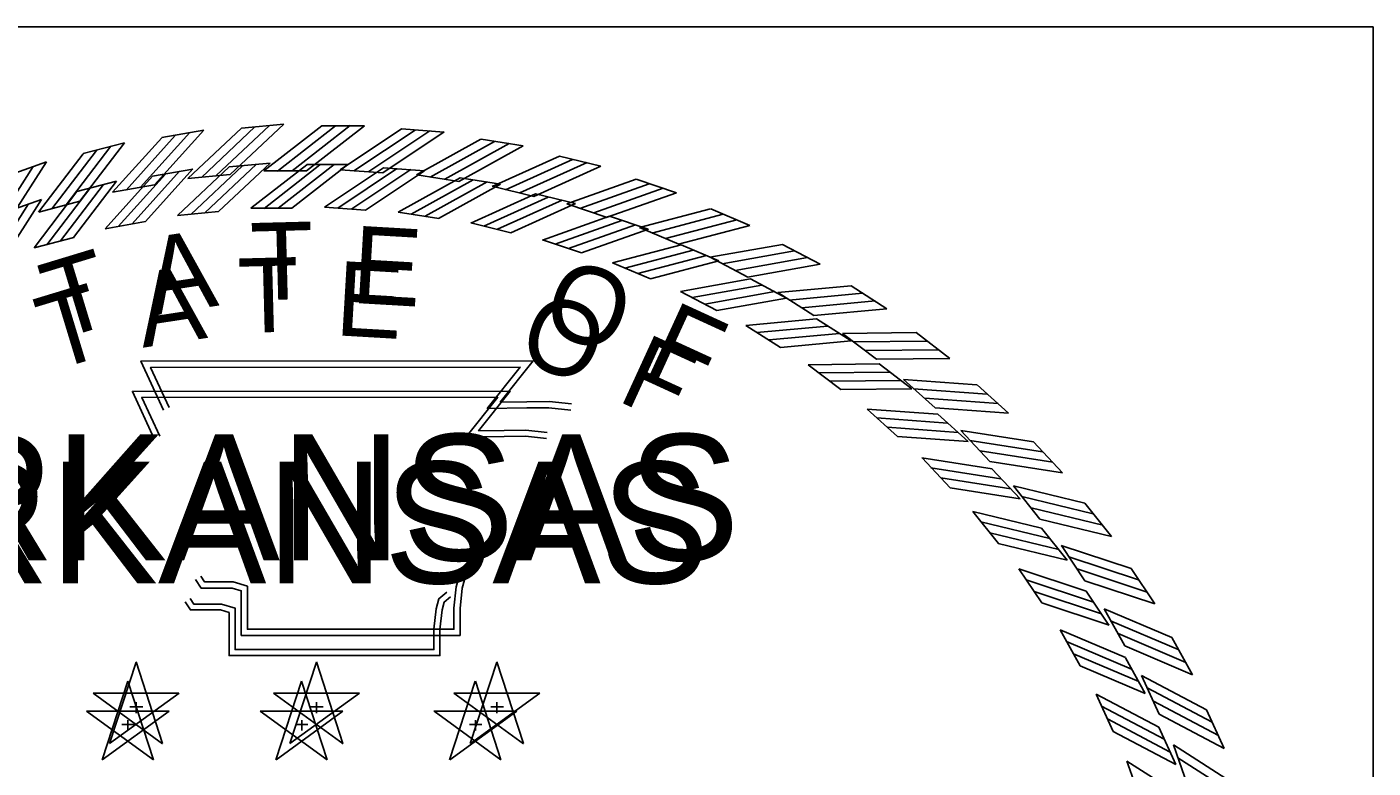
# Model space of a CAD drawing. Extents: x 0 to 1228740, y 0 to 152440.
# Drawn here: x 35.691 to 37.414, y 24.11 to 25.058 of the extents above; entities that cross this region are included whole.
import ezdxf

# ---------------------------------------------------------------- set-up
doc = ezdxf.new("R2010")
doc.units = 0
for name, color, linetype in [('R_No Plot', 7, 'Continuous'), ('STAMP', 7, 'Continuous'), ('STAMP_PP', 7, 'Continuous')]:
    doc.layers.add(name, color=color, linetype=linetype)

msp = doc.modelspace()

# ---------------------------------------------------------------- linework, layer by layer
at = {"layer": 'R_No Plot'}
msp.add_lwpolyline([(34.6722, 25.0583), (37.4139, 25.0583), (37.4139, 22.3166), (34.6722, 22.3166)], close=True, dxfattribs=at)
at = {"layer": 'STAMP'}
for p, q in [((35.8523, 24.8673), (35.9039, 24.8764)), ((35.9503, 24.879), (36.0025, 24.8838)), ((36.0496, 24.882), (36.102, 24.882)), ((36.1477, 24.878), (36.2, 24.8742)), ((35.7555, 24.8475), (35.8062, 24.8609)), ((36.2457, 24.8653), (36.2974, 24.8572)), ((36.3423, 24.8445), (36.3932, 24.8321)), ((35.6607, 24.8198), (35.7101, 24.8373)), ((35.8842, 24.8169), (35.9365, 24.8218)), ((35.9781, 24.8262), (36.0306, 24.8262)), ((36.0723, 24.8277), (36.1247, 24.8238)), ((36.1664, 24.8213), (36.2183, 24.8132)), ((35.7915, 24.8), (35.8432, 24.8091)), ((36.2596, 24.8073), (36.3106, 24.7949)), ((36.4368, 24.8159), (36.4865, 24.7993)), ((35.7005, 24.7754), (35.7513, 24.7888)), ((36.3513, 24.7856), (36.4012, 24.769)), ((36.5286, 24.7795), (36.5768, 24.7589)), ((36.4409, 24.7564), (36.4892, 24.7357)), ((36.6171, 24.7357), (36.6635, 24.7111)), ((36.5279, 24.7198), (36.5743, 24.6953)), ((36.7017, 24.6847), (36.7459, 24.6564)), ((36.6115, 24.6763), (36.6557, 24.6479)), ((36.6912, 24.6259), (36.7329, 24.5941)), ((36.7818, 24.6269), (36.8235, 24.5951)), ((36.7664, 24.5692), (36.8054, 24.534)), ((36.8569, 24.5626), (36.8958, 24.5275)), ((36.8368, 24.5065), (36.8727, 24.4681)), ((36.9264, 24.4924), (36.9622, 24.4542)), ((36.9017, 24.4381), (36.9344, 24.3969)), ((36.9898, 24.4167), (37.0224, 24.3757)), ((36.9608, 24.3646), (36.9899, 24.3209)), ((37.0468, 24.336), (37.0759, 24.2924)), ((37.0136, 24.2865), (37.039, 24.2406)), ((37.097, 24.2509), (37.1223, 24.2051)), ((35.8206, 24.2208), (35.7878, 24.1202)), ((35.8532, 24.1203), (35.8206, 24.2209)), ((36.0429, 24.2208), (36.0101, 24.1202)), ((36.0755, 24.1203), (36.0429, 24.2209)), ((36.2651, 24.2208), (36.2323, 24.1202)), ((36.2978, 24.1203), (36.2652, 24.2209)), ((37.0597, 24.2043), (37.0812, 24.1564)), ((35.8734, 24.1824), (35.7676, 24.1825)), ((35.7677, 24.1824), (35.8533, 24.1201)), ((35.7879, 24.1203), (35.8736, 24.1824)), ((35.8207, 24.1711), (35.8207, 24.1579)), ((36.0957, 24.1824), (35.9899, 24.1825)), ((35.99, 24.1824), (36.0755, 24.1201)), ((36.0102, 24.1203), (36.0958, 24.1824)), ((36.043, 24.1711), (36.043, 24.1579)), ((36.318, 24.1824), (36.2122, 24.1825)), ((36.2123, 24.1824), (36.2978, 24.1201)), ((36.2325, 24.1203), (36.3181, 24.1824)), ((36.2652, 24.1711), (36.2652, 24.1579)), ((35.813, 24.1655), (35.8288, 24.1655)), ((36.0353, 24.1655), (36.051, 24.1655)), ((36.2576, 24.1655), (36.2733, 24.1655)), ((37.1399, 24.162), (37.1614, 24.1142)), ((37.0989, 24.1186), (37.1164, 24.0691))]:
    msp.add_line(p, q, dxfattribs=at)
for points in [[(35.826, 24.8063), (35.8867, 24.8736)], [(35.8432, 24.8091), (35.9039, 24.8765)], [(35.8842, 24.8169), (35.9503, 24.879)], [(35.901, 24.8183), (35.9671, 24.8804)], [(35.9191, 24.8204), (35.9852, 24.8824)], [(35.9365, 24.8218), (36.0026, 24.8839)], [(35.978, 24.8261), (36.0495, 24.8819)], [(35.9949, 24.826), (36.0664, 24.8818)], [(36.0131, 24.8264), (36.0846, 24.8822)], [(36.0305, 24.8262), (36.102, 24.882)], [(36.0722, 24.8276), (36.1476, 24.878)], [(36.0891, 24.8262), (36.1645, 24.8766)], [(36.1072, 24.8253), (36.1826, 24.8757)], [(36.1246, 24.8239), (36.2, 24.8742)], [(35.7343, 24.7845), (35.7893, 24.8566)], [(35.7512, 24.7888), (35.8062, 24.8609)], [(35.7915, 24.7999), (35.8522, 24.8673)], [(35.8081, 24.8027), (35.8688, 24.87)], [(36.1663, 24.8213), (36.2456, 24.8653)], [(36.1829, 24.8185), (36.2622, 24.8625)], [(36.201, 24.8161), (36.2803, 24.8601)], [(36.2182, 24.8132), (36.2975, 24.8572)], [(35.7005, 24.7754), (35.7554, 24.8475)], [(35.7168, 24.7795), (35.7718, 24.8516)], [(36.2595, 24.8072), (36.3422, 24.8445)], [(36.2759, 24.8031), (36.3585, 24.8404)], [(35.6448, 24.7553), (35.6936, 24.8317)], [(35.6613, 24.761), (35.7101, 24.8374)], [(36.2936, 24.7992), (36.3763, 24.8365)], [(36.3106, 24.7949), (36.3932, 24.8322)], [(36.3512, 24.7855), (36.4367, 24.8159)], [(36.3672, 24.7801), (36.4527, 24.8104)], [(36.3846, 24.7747), (36.47, 24.805)], [(36.4011, 24.769), (36.4866, 24.7993)], [(36.4409, 24.7563), (36.5285, 24.7795)], [(36.4563, 24.7496), (36.544, 24.7727)], [(36.4732, 24.7428), (36.5609, 24.7659)], [(36.4892, 24.7358), (36.5769, 24.7589)], [(36.5278, 24.7198), (36.6171, 24.7357)], [(36.5426, 24.7118), (36.6319, 24.7276)], [(36.5589, 24.7036), (36.6482, 24.7195)], [(36.5742, 24.6953), (36.6635, 24.7112)], [(36.6114, 24.6763), (36.7017, 24.6847)], [(36.6255, 24.667), (36.7158, 24.6754)], [(36.641, 24.6576), (36.7313, 24.666)], [(36.6557, 24.648), (36.7459, 24.6564)], [(36.6911, 24.6259), (36.7818, 24.6269)], [(36.7044, 24.6156), (36.7951, 24.6165)], [(36.7191, 24.6049), (36.8098, 24.6058)], [(35.8543, 24.5312), (35.8264, 24.5917), (36.3097, 24.592), (36.2693, 24.5413), (36.3021, 24.5417), (36.3296, 24.5421), (36.357, 24.5391)], [(35.8613, 24.5344), (35.8384, 24.5841), (36.2938, 24.5843), (36.2533, 24.5334), (36.3022, 24.534), (36.3292, 24.5344), (36.3561, 24.5315)], [(36.7329, 24.5941), (36.8236, 24.5951)], [(36.7664, 24.5692), (36.8568, 24.5626)], [(36.7788, 24.5578), (36.8692, 24.5512)], [(36.7926, 24.5459), (36.883, 24.5393)], [(36.8054, 24.5341), (36.8958, 24.5275)], [(36.8367, 24.5065), (36.9263, 24.4925)], [(36.8481, 24.4941), (36.9377, 24.48)], [(36.8609, 24.4811), (36.9505, 24.467)], [(36.8727, 24.4682), (36.9623, 24.4542)], [(36.9016, 24.4381), (36.9898, 24.4168)], [(36.912, 24.4248), (37.0001, 24.4034)], [(36.9236, 24.4108), (37.0117, 24.3894)], [(36.9343, 24.397), (37.0225, 24.3757)], [(36.9607, 24.3646), (37.0467, 24.3361)], [(36.9699, 24.3505), (37.056, 24.322)], [(36.2335, 24.3287), (36.2253, 24.322), (36.2226, 24.312), (36.2198, 24.2869), (36.2198, 24.2535), (35.95, 24.2535), (35.95, 24.2986), (35.95, 24.3086), (35.9391, 24.312), (35.9007, 24.312), (35.8939, 24.3224)], [(36.2287, 24.3346), (36.2186, 24.3264), (36.215, 24.3134), (36.2122, 24.2873), (36.2122, 24.2612), (35.9577, 24.2612), (35.9577, 24.2986), (35.9577, 24.3143), (35.9402, 24.3196), (35.9048, 24.3196), (35.9003, 24.3266)], [(36.9803, 24.3356), (37.0664, 24.307)], [(36.9899, 24.321), (37.076, 24.2924)], [(37.0135, 24.2865), (37.0969, 24.251)], [(37.0215, 24.2717), (37.1049, 24.2361)], [(37.0307, 24.256), (37.1141, 24.2204)], [(37.039, 24.2406), (37.1224, 24.2051)], [(37.0596, 24.2044), (37.1398, 24.162)], [(37.0664, 24.1889), (37.1466, 24.1466)], [(37.0742, 24.1725), (37.1544, 24.1301)], [(37.0813, 24.1565), (37.1614, 24.1141)], [(37.0988, 24.1186), (37.1753, 24.0698)]]:
    msp.add_lwpolyline(points, dxfattribs=at)
at = {"layer": 'STAMP_PP'}
for p, q in [((35.864, 24.9166), (35.9176, 24.9261)), ((35.9659, 24.9288), (36.02, 24.9338)), ((36.0689, 24.9318), (36.1233, 24.9318)), ((36.1708, 24.9277), (36.2251, 24.9237)), ((35.7636, 24.8961), (35.8162, 24.9099)), ((36.2725, 24.9145), (36.3263, 24.9061)), ((36.3728, 24.893), (36.4256, 24.8801)), ((35.6651, 24.8673), (35.7164, 24.8855)), ((35.9946, 24.8739), (36.0492, 24.8739)), ((36.0925, 24.8754), (36.1469, 24.8714)), ((35.801, 24.8467), (35.8547, 24.8562)), ((35.8972, 24.8643), (35.9516, 24.8693)), ((36.1902, 24.8689), (36.244, 24.8604)), ((36.4709, 24.8632), (36.5225, 24.846)), ((36.2869, 24.8543), (36.3399, 24.8414)), ((35.7065, 24.8212), (35.7592, 24.8351)), ((36.3822, 24.8317), (36.4339, 24.8145)), ((36.5663, 24.8254), (36.6163, 24.804)), ((36.4752, 24.8014), (36.5254, 24.78)), ((36.6582, 24.7799), (36.7063, 24.7545)), ((36.5655, 24.7635), (36.6137, 24.738)), ((36.6523, 24.7182), (36.6982, 24.6888)), ((36.746, 24.727), (36.7918, 24.6976)), ((36.735, 24.666), (36.7784, 24.6329)), ((36.8292, 24.667), (36.8724, 24.6339)), ((36.8132, 24.6071), (36.8537, 24.5705)), ((36.9071, 24.6003), (36.9475, 24.5638)), ((36.8862, 24.5419), (36.9235, 24.5022)), ((36.9793, 24.5274), (37.0165, 24.4877)), ((36.9536, 24.471), (36.9875, 24.4282)), ((37.0451, 24.4488), (37.079, 24.4062)), ((37.015, 24.3947), (37.0452, 24.3493)), ((37.1043, 24.365), (37.1345, 24.3197)), ((37.0698, 24.3136), (37.0962, 24.2659)), ((37.1564, 24.2766), (37.1827, 24.229)), ((35.8311, 24.2453), (35.7971, 24.1409)), ((35.8651, 24.141), (35.8312, 24.2455)), ((36.0619, 24.2453), (36.0279, 24.1409)), ((36.0958, 24.141), (36.062, 24.2455)), ((36.2927, 24.2453), (36.2587, 24.1409)), ((36.3266, 24.141), (36.2928, 24.2455)), ((37.1177, 24.2282), (37.14, 24.1785)), ((35.886, 24.2055), (35.7762, 24.2056)), ((35.7763, 24.2055), (35.8651, 24.1408)), ((35.7972, 24.141), (35.8862, 24.2054)), ((36.1168, 24.2055), (36.007, 24.2056)), ((36.0071, 24.2055), (36.0959, 24.1408)), ((36.028, 24.141), (36.1169, 24.2054)), ((36.3476, 24.2055), (36.2377, 24.2056)), ((36.2378, 24.2055), (36.3266, 24.1408)), ((36.2588, 24.141), (36.3477, 24.2054)), ((35.8233, 24.1879), (35.8397, 24.1879)), ((35.8312, 24.1938), (35.8312, 24.18)), ((36.0541, 24.1879), (36.0704, 24.1879)), ((36.062, 24.1938), (36.062, 24.18)), ((36.2849, 24.1879), (36.3012, 24.1879)), ((36.2928, 24.1938), (36.2928, 24.18)), ((37.2009, 24.1843), (37.2232, 24.1347)), ((37.1584, 24.1392), (37.1766, 24.0878))]:
    msp.add_line(p, q, dxfattribs=at)
for points in [[(35.8546, 24.8562), (35.9177, 24.9261)], [(35.8972, 24.8643), (35.9658, 24.9287)], [(35.9146, 24.8657), (35.9832, 24.9302)], [(35.9334, 24.8679), (36.002, 24.9323)], [(35.9515, 24.8693), (36.0201, 24.9338)], [(35.9946, 24.8739), (36.0688, 24.9318)], [(36.0121, 24.8737), (36.0863, 24.9316)], [(36.031, 24.8741), (36.1052, 24.932)], [(36.0491, 24.874), (36.1234, 24.9318)], [(36.0924, 24.8754), (36.1707, 24.9277)], [(36.1099, 24.8739), (36.1882, 24.9262)], [(36.1288, 24.873), (36.2071, 24.9253)], [(36.1468, 24.8715), (36.2251, 24.9238)], [(35.7591, 24.8351), (35.8162, 24.91)], [(35.8009, 24.8466), (35.864, 24.9165)], [(35.8182, 24.8495), (35.8812, 24.9194)], [(35.8367, 24.8532), (35.8998, 24.9231)], [(36.1901, 24.8688), (36.2724, 24.9145)], [(36.2074, 24.866), (36.2897, 24.9116)], [(36.2261, 24.8634), (36.3084, 24.9091)], [(35.7064, 24.8211), (35.7635, 24.896)], [(35.7234, 24.8254), (35.7805, 24.9003)], [(35.7416, 24.8306), (35.7986, 24.9055)], [(36.244, 24.8604), (36.3263, 24.9061)], [(36.2869, 24.8542), (36.3727, 24.8929)], [(35.6486, 24.8003), (35.6993, 24.8796)], [(35.6658, 24.8062), (35.7164, 24.8855)], [(36.3038, 24.8499), (36.3897, 24.8886)], [(36.3223, 24.8459), (36.4081, 24.8846)], [(36.3399, 24.8414), (36.4257, 24.8801)], [(36.3821, 24.8317), (36.4708, 24.8632)], [(36.3987, 24.826), (36.4874, 24.8575)], [(36.4167, 24.8204), (36.5055, 24.8519)], [(36.4339, 24.8146), (36.5226, 24.846)], [(36.4752, 24.8014), (36.5662, 24.8254)], [(36.4912, 24.7943), (36.5822, 24.8184)], [(36.5087, 24.7873), (36.5998, 24.8113)], [(36.5253, 24.78), (36.6164, 24.8041)], [(36.5654, 24.7635), (36.6581, 24.7799)], [(36.5808, 24.7551), (36.6735, 24.7716)], [(36.5977, 24.7467), (36.6904, 24.7631)], [(36.6136, 24.738), (36.7063, 24.7545)], [(36.6522, 24.7182), (36.7459, 24.727)], [(36.6669, 24.7087), (36.7606, 24.7174)], [(36.683, 24.6988), (36.7767, 24.7076)], [(36.6982, 24.6889), (36.7919, 24.6976)], [(36.735, 24.666), (36.8291, 24.667)], [(36.7488, 24.6552), (36.8429, 24.6562)], [(36.764, 24.6441), (36.8582, 24.6451)], [(36.7784, 24.633), (36.8725, 24.6339)], [(35.8662, 24.5677), (35.8372, 24.6305), (36.339, 24.6308), (36.2971, 24.5781), (36.3311, 24.5785), (36.3596, 24.5789), (36.3881, 24.5758)], [(35.8734, 24.571), (35.8496, 24.6225), (36.3225, 24.6228), (36.2804, 24.5699), (36.3312, 24.5706), (36.3592, 24.5709), (36.3872, 24.5679)], [(36.8131, 24.6071), (36.907, 24.6003)], [(36.826, 24.5952), (36.9199, 24.5884)], [(36.8403, 24.5829), (36.9342, 24.5761)], [(36.8536, 24.5706), (36.9475, 24.5638)], [(36.8862, 24.5419), (36.9792, 24.5274)], [(36.898, 24.5291), (36.991, 24.5145)], [(36.9112, 24.5156), (37.0043, 24.501)], [(36.9235, 24.5022), (37.0165, 24.4877)], [(36.9536, 24.471), (37.0451, 24.4488)], [(36.9643, 24.4572), (37.0558, 24.435)], [(36.9764, 24.4426), (37.0679, 24.4204)], [(36.9875, 24.4283), (37.079, 24.4061)], [(37.0149, 24.3947), (37.1042, 24.365)], [(37.0245, 24.38), (37.1138, 24.3504)], [(36.2599, 24.3574), (36.2513, 24.3504), (36.2485, 24.34), (36.2457, 24.314), (36.2457, 24.2793), (35.9656, 24.2793), (35.9656, 24.3261), (35.9656, 24.3365), (35.9542, 24.34), (35.9143, 24.34), (35.9073, 24.3508)], [(36.2549, 24.3636), (36.2444, 24.355), (36.2407, 24.3415), (36.2377, 24.3144), (36.2377, 24.2873), (35.9735, 24.2873), (35.9735, 24.3261), (35.9735, 24.3424), (35.9554, 24.348), (35.9186, 24.348), (35.9139, 24.3552)], [(37.0353, 24.3646), (37.1246, 24.3349)], [(37.0452, 24.3494), (37.1345, 24.3197)], [(37.0697, 24.3136), (37.1563, 24.2767)], [(37.078, 24.2982), (37.1646, 24.2613)], [(37.0875, 24.2819), (37.1741, 24.2449)], [(37.0962, 24.2659), (37.1827, 24.229)], [(37.1176, 24.2283), (37.2009, 24.1843)], [(37.1246, 24.2122), (37.2079, 24.1683)], [(37.1328, 24.1952), (37.216, 24.1512)], [(37.1401, 24.1786), (37.2233, 24.1346)], [(37.1583, 24.1393), (37.2376, 24.0886)], [(37.164, 24.1227), (37.2433, 24.072)]]:
    msp.add_lwpolyline(points, dxfattribs=at)

# ---------------------------------------------------------------- texts
at = {"layer": 'STAMP'}
for s, rotation, p in [('T', 1.4789, (35.9627, 24.6665)), ('E', 356.672, (36.0847, 24.6637)), ('A', 8.6788, (35.8396, 24.6476)), ('T', 16.9015, (35.7238, 24.6174)), ('O', 341.2218, (36.3162, 24.631)), ('F', 335.3628, (36.4447, 24.5807))]:
    msp.add_text(s, height=0.0953, rotation=rotation, dxfattribs=at).set_placement(p)
msp.add_text('ARKANSAS', height=0.15559, dxfattribs=at).set_placement((35.4313, 24.3461))
at = {"layer": 'STAMP_PP'}
for s, rotation, p in [('T', 1.4789, (35.9787, 24.7082)), ('E', 356.672, (36.1054, 24.7052)), ('A', 8.6788, (35.8509, 24.6885)), ('T', 16.9015, (35.7307, 24.6571)), ('O', 341.2218, (36.3457, 24.6712)), ('F', 335.3628, (36.4791, 24.619))]:
    msp.add_text(s, height=0.099, rotation=rotation, dxfattribs=at).set_placement(p)
msp.add_text('ARKANSAS', height=0.16155, dxfattribs=at).set_placement((35.427, 24.3754))

doc.saveas('drawing.dxf')
